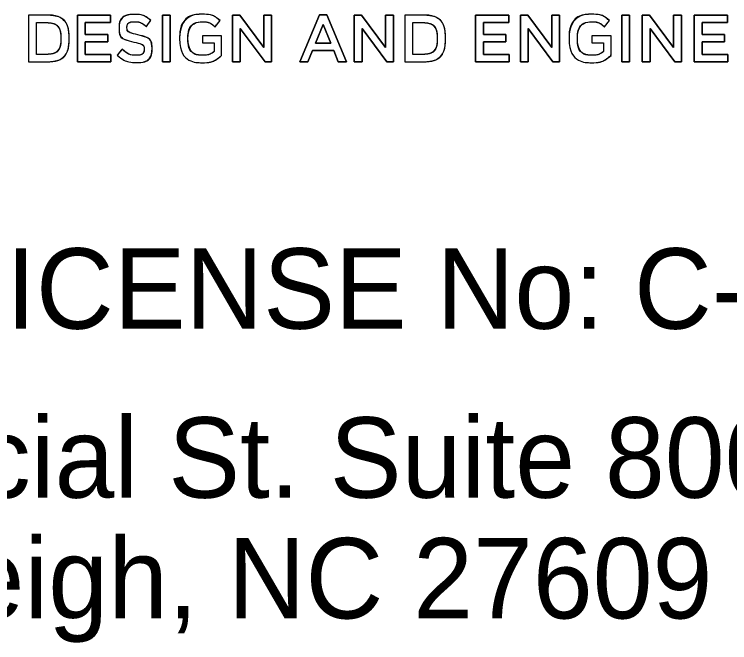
# Model space of a CAD drawing. Extents: x 1184121 to 1184360, y 1246506 to 1246661.
# Drawn here: x 1184348.947 to 1184353.836, y 1246633.134 to 1246637.429 of the extents above; entities that cross this region are included whole.
import ezdxf

# ---------------------------------------------------------------- set-up
doc = ezdxf.new("R2010")
doc.units = 0
doc.layers.add('Sheet Plan CELL', color=7, linetype='Continuous')

msp = doc.modelspace()

# ---------------------------------------------------------------- linework, layer by layer
at = {"layer": 'Sheet Plan CELL'}
for p, q in [((1184349.8503, 1246637.3459), (1184349.8793, 1246637.3884)), ((1184350.3189, 1246637.3436), (1184350.3531, 1246637.3861)), ((1184352.98, 1246637.3436), (1184353.0142, 1246637.3861)), ((1184349.6633, 1246637.3358), (1184349.6633, 1246637.3349)), ((1184349.7171, 1246637.34), (1184349.7171, 1246637.3409)), ((1184349.2652, 1246637.2641), (1184349.2652, 1246637.2632)), ((1184349.3218, 1246637.2641), (1184349.3218, 1246637.265)), ((1184350.0771, 1246637.2641), (1184350.0771, 1246637.2632)), ((1184350.1336, 1246637.2641), (1184350.1336, 1246637.265)), ((1184351.8373, 1246637.2641), (1184351.8373, 1246637.2632)), ((1184351.8938, 1246637.2641), (1184351.8938, 1246637.265)), ((1184352.7382, 1246637.2641), (1184352.7382, 1246637.2632)), ((1184352.7947, 1246637.2641), (1184352.7947, 1246637.265)), ((1184349.6834, 1246637.1911), (1184349.651, 1246637.1509)), ((1184349.8346, 1246637.1906), (1184349.8346, 1246637.1897)), ((1184349.8884, 1246637.1952), (1184349.8884, 1246637.1961))]:
    msp.add_line(p, q, dxfattribs=at)
for points in [[(1184349.1588, 1246637.424), (1184349.0444, 1246637.424), (1184349.0444, 1246637.1043), (1184349.1588, 1246637.1043)], [(1184349.3782, 1246637.424), (1184349.6055, 1246637.424), (1184349.6055, 1246637.3737), (1184349.432, 1246637.3737), (1184349.432, 1246637.2906), (1184349.5858, 1246637.2906), (1184349.5858, 1246637.2404), (1184349.432, 1246637.2404), (1184349.432, 1246637.1545), (1184349.6077, 1246637.1545), (1184349.6077, 1246637.1043), (1184349.3782, 1246637.1043), (1184349.3782, 1246637.424)], [(1184349.3782, 1246637.1043), (1184349.6077, 1246637.1043), (1184349.6077, 1246637.1545), (1184349.432, 1246637.1545), (1184349.432, 1246637.2404), (1184349.5858, 1246637.2404), (1184349.5858, 1246637.2906), (1184349.432, 1246637.2906), (1184349.432, 1246637.3737), (1184349.6055, 1246637.3737), (1184349.6055, 1246637.424), (1184349.3782, 1246637.424), (1184349.3782, 1246637.1043)], [(1184349.9593, 1246637.424), (1184350.0132, 1246637.424), (1184350.0132, 1246637.1043), (1184349.9593, 1246637.1043), (1184349.9593, 1246637.424)], [(1184349.9593, 1246637.1043), (1184350.0132, 1246637.1043), (1184350.0132, 1246637.424), (1184349.9593, 1246637.424), (1184349.9593, 1246637.1043)], [(1184350.4384, 1246637.424), (1184350.4884, 1246637.424), (1184350.6527, 1246637.2029), (1184350.6527, 1246637.424), (1184350.7057, 1246637.424), (1184350.7057, 1246637.1043), (1184350.6605, 1246637.1043), (1184350.4914, 1246637.3317), (1184350.4914, 1246637.1043), (1184350.4384, 1246637.1043), (1184350.4384, 1246637.424)], [(1184350.4384, 1246637.1043), (1184350.4914, 1246637.1043), (1184350.4914, 1246637.3317), (1184350.6605, 1246637.1043), (1184350.7057, 1246637.1043), (1184350.7057, 1246637.424), (1184350.6527, 1246637.424), (1184350.6527, 1246637.2029), (1184350.4884, 1246637.424), (1184350.4384, 1246637.424), (1184350.4384, 1246637.1043)], [(1184351.0332, 1246637.4263), (1184351.0832, 1246637.4263), (1184351.2181, 1246637.1043), (1184351.1611, 1246637.1043), (1184351.13, 1246637.1815), (1184350.985, 1246637.1815), (1184350.9535, 1246637.1043), (1184350.8983, 1246637.1043), (1184351.0332, 1246637.4263)], [(1184350.8983, 1246637.1043), (1184350.9535, 1246637.1043), (1184350.985, 1246637.1815), (1184351.13, 1246637.1815), (1184351.1611, 1246637.1043), (1184351.2181, 1246637.1043), (1184351.0832, 1246637.4263), (1184351.0332, 1246637.4263), (1184350.8983, 1246637.1043)], [(1184351.2706, 1246637.424), (1184351.3205, 1246637.424), (1184351.4847, 1246637.2029), (1184351.4847, 1246637.424), (1184351.5378, 1246637.424), (1184351.5378, 1246637.1043), (1184351.4927, 1246637.1043), (1184351.3236, 1246637.3317), (1184351.3236, 1246637.1043), (1184351.2706, 1246637.1043), (1184351.2706, 1246637.424)], [(1184351.2706, 1246637.1043), (1184351.3236, 1246637.1043), (1184351.3236, 1246637.3317), (1184351.4927, 1246637.1043), (1184351.5378, 1246637.1043), (1184351.5378, 1246637.424), (1184351.4847, 1246637.424), (1184351.4847, 1246637.2029), (1184351.3205, 1246637.424), (1184351.2706, 1246637.424), (1184351.2706, 1246637.1043)], [(1184351.7309, 1246637.424), (1184351.6166, 1246637.424), (1184351.6166, 1246637.1043), (1184351.7309, 1246637.1043)], [(1184352.0992, 1246637.424), (1184352.3265, 1246637.424), (1184352.3265, 1246637.3737), (1184352.1531, 1246637.3737), (1184352.1531, 1246637.2906), (1184352.3068, 1246637.2906), (1184352.3068, 1246637.2404), (1184352.1531, 1246637.2404), (1184352.1531, 1246637.1545), (1184352.3287, 1246637.1545), (1184352.3287, 1246637.1043), (1184352.0992, 1246637.1043), (1184352.0992, 1246637.424)], [(1184352.0992, 1246637.1043), (1184352.3287, 1246637.1043), (1184352.3287, 1246637.1545), (1184352.1531, 1246637.1545), (1184352.1531, 1246637.2404), (1184352.3068, 1246637.2404), (1184352.3068, 1246637.2906), (1184352.1531, 1246637.2906), (1184352.1531, 1246637.3737), (1184352.3265, 1246637.3737), (1184352.3265, 1246637.424), (1184352.0992, 1246637.424), (1184352.0992, 1246637.1043)], [(1184352.4058, 1246637.424), (1184352.4557, 1246637.424), (1184352.62, 1246637.2029), (1184352.62, 1246637.424), (1184352.673, 1246637.424), (1184352.673, 1246637.1043), (1184352.6279, 1246637.1043), (1184352.4588, 1246637.3317), (1184352.4588, 1246637.1043), (1184352.4058, 1246637.1043), (1184352.4058, 1246637.424)], [(1184352.4058, 1246637.1043), (1184352.4588, 1246637.1043), (1184352.4588, 1246637.3317), (1184352.6279, 1246637.1043), (1184352.673, 1246637.1043), (1184352.673, 1246637.424), (1184352.62, 1246637.424), (1184352.62, 1246637.2029), (1184352.4557, 1246637.424), (1184352.4058, 1246637.424), (1184352.4058, 1246637.1043)], [(1184353.0982, 1246637.424), (1184353.1521, 1246637.424), (1184353.1521, 1246637.1043), (1184353.0982, 1246637.1043), (1184353.0982, 1246637.424)], [(1184353.0982, 1246637.1043), (1184353.1521, 1246637.1043), (1184353.1521, 1246637.424), (1184353.0982, 1246637.424), (1184353.0982, 1246637.1043)], [(1184353.2383, 1246637.424), (1184353.2883, 1246637.424), (1184353.4525, 1246637.2029), (1184353.4525, 1246637.424), (1184353.5055, 1246637.424), (1184353.5055, 1246637.1043), (1184353.4604, 1246637.1043), (1184353.2914, 1246637.3317), (1184353.2914, 1246637.1043), (1184353.2383, 1246637.1043), (1184353.2383, 1246637.424)], [(1184353.2383, 1246637.1043), (1184353.2914, 1246637.1043), (1184353.2914, 1246637.3317), (1184353.4604, 1246637.1043), (1184353.5055, 1246637.1043), (1184353.5055, 1246637.424), (1184353.4525, 1246637.424), (1184353.4525, 1246637.2029), (1184353.2883, 1246637.424), (1184353.2383, 1246637.424), (1184353.2383, 1246637.1043)], [(1184353.5931, 1246637.424), (1184353.8204, 1246637.424), (1184353.8204, 1246637.3737), (1184353.6469, 1246637.3737), (1184353.6469, 1246637.2906), (1184353.8007, 1246637.2906), (1184353.8007, 1246637.2404), (1184353.6469, 1246637.2404), (1184353.6469, 1246637.1545), (1184353.8226, 1246637.1545), (1184353.8226, 1246637.1043), (1184353.5931, 1246637.1043), (1184353.5931, 1246637.424)], [(1184353.5931, 1246637.1043), (1184353.8226, 1246637.1043), (1184353.8226, 1246637.1545), (1184353.6469, 1246637.1545), (1184353.6469, 1246637.2404), (1184353.8007, 1246637.2404), (1184353.8007, 1246637.2906), (1184353.6469, 1246637.2906), (1184353.6469, 1246637.3737), (1184353.8204, 1246637.3737), (1184353.8204, 1246637.424), (1184353.5931, 1246637.424), (1184353.5931, 1246637.1043)], [(1184349.1588, 1246637.1554), (1184349.0983, 1246637.1554), (1184349.0983, 1246637.3728), (1184349.1588, 1246637.3728)], [(1184351.1103, 1246637.2313), (1184351.0573, 1246637.3591), (1184351.0048, 1246637.2313), (1184351.1103, 1246637.2313)], [(1184351.0048, 1246637.2313), (1184351.0573, 1246637.3591), (1184351.1103, 1246637.2313), (1184351.0048, 1246637.2313)], [(1184351.7309, 1246637.1554), (1184351.6705, 1246637.1554), (1184351.6705, 1246637.3728), (1184351.7309, 1246637.3728)], [(1184350.364, 1246637.1486), (1184350.364, 1246637.2829), (1184350.2335, 1246637.2829), (1184350.2335, 1246637.234), (1184350.312, 1246637.234), (1184350.312, 1246637.1742)], [(1184353.0251, 1246637.1486), (1184353.0251, 1246637.2829), (1184352.8945, 1246637.2829), (1184352.8945, 1246637.234), (1184352.973, 1246637.234), (1184352.973, 1246637.1742)]]:
    msp.add_lwpolyline(points, dxfattribs=at)
for points, degree in [([(1184349.0444, 1246637.424), (1184349.0444, 1246637.424), (1184349.1588, 1246637.424), (1184349.1588, 1246637.424), (1184349.2552, 1246637.424), (1184349.3218, 1246637.355), (1184349.3218, 1246637.265), (1184349.3218, 1246637.265), (1184349.3218, 1246637.2641), (1184349.3218, 1246637.2641), (1184349.3218, 1246637.1742), (1184349.2552, 1246637.1043), (1184349.1588, 1246637.1043), (1184349.1588, 1246637.1043), (1184349.0444, 1246637.1043), (1184349.0444, 1246637.1043), (1184349.0444, 1246637.1043), (1184349.0444, 1246637.424), (1184349.0444, 1246637.424)], 3), ([(1184349.3218, 1246637.265), (1184349.3218, 1246637.355), (1184349.2552, 1246637.424), (1184349.1588, 1246637.424)], 2), ([(1184349.651, 1246637.1509), (1184349.651, 1246637.1509), (1184349.6834, 1246637.1911), (1184349.6834, 1246637.1911), (1184349.7128, 1246637.1646), (1184349.7425, 1246637.1495), (1184349.7803, 1246637.1495), (1184349.8135, 1246637.1495), (1184349.8346, 1246637.166), (1184349.8346, 1246637.1897), (1184349.8346, 1246637.1897), (1184349.8346, 1246637.1906), (1184349.8346, 1246637.1906), (1184349.8346, 1246637.2134), (1184349.8223, 1246637.2258), (1184349.7653, 1246637.2395), (1184349.7001, 1246637.2559), (1184349.6633, 1246637.276), (1184349.6633, 1246637.3349), (1184349.6633, 1246637.3349), (1184349.6633, 1246637.3358), (1184349.6633, 1246637.3358), (1184349.6633, 1246637.3907), (1184349.7071, 1246637.4286), (1184349.768, 1246637.4286), (1184349.8127, 1246637.4286), (1184349.8481, 1246637.4144), (1184349.8793, 1246637.3884), (1184349.8793, 1246637.3884), (1184349.8503, 1246637.3459), (1184349.8503, 1246637.3459), (1184349.8227, 1246637.3674), (1184349.7952, 1246637.3788), (1184349.7671, 1246637.3788), (1184349.7356, 1246637.3788), (1184349.7171, 1246637.3619), (1184349.7171, 1246637.3409), (1184349.7171, 1246637.3409), (1184349.7171, 1246637.34), (1184349.7171, 1246637.34), (1184349.7171, 1246637.3153), (1184349.7312, 1246637.3043), (1184349.7903, 1246637.2897), (1184349.8551, 1246637.2733), (1184349.8884, 1246637.2491), (1184349.8884, 1246637.1961), (1184349.8884, 1246637.1961), (1184349.8884, 1246637.1952), (1184349.8884, 1246637.1952), (1184349.8884, 1246637.1354), (1184349.8433, 1246637.0997), (1184349.7789, 1246637.0997), (1184349.732, 1246637.0997), (1184349.6878, 1246637.1166), (1184349.651, 1246637.1509)], 3), ([(1184349.8793, 1246637.3884), (1184349.8481, 1246637.4144), (1184349.8127, 1246637.4286), (1184349.768, 1246637.4286), (1184349.7071, 1246637.4286), (1184349.6633, 1246637.3907), (1184349.6633, 1246637.3358)], 3), ([(1184350.0771, 1246637.2632), (1184350.0771, 1246637.2632), (1184350.0771, 1246637.2641), (1184350.0771, 1246637.2641), (1184350.0771, 1246637.3537), (1184350.1428, 1246637.4295), (1184350.2352, 1246637.4295), (1184350.2887, 1246637.4295), (1184350.3216, 1246637.4139), (1184350.3531, 1246637.3861), (1184350.3531, 1246637.3861), (1184350.3189, 1246637.3436), (1184350.3189, 1246637.3436), (1184350.2953, 1246637.3646), (1184350.2721, 1246637.3779), (1184350.2331, 1246637.3779), (1184350.1766, 1246637.3779), (1184350.1336, 1246637.3263), (1184350.1336, 1246637.265), (1184350.1336, 1246637.265), (1184350.1336, 1246637.2641), (1184350.1336, 1246637.2641), (1184350.1336, 1246637.1984), (1184350.1753, 1246637.15), (1184350.2379, 1246637.15), (1184350.2668, 1246637.15), (1184350.2931, 1246637.1596), (1184350.312, 1246637.1742), (1184350.312, 1246637.1742), (1184350.312, 1246637.234), (1184350.312, 1246637.234), (1184350.312, 1246637.234), (1184350.2335, 1246637.234), (1184350.2335, 1246637.234), (1184350.2335, 1246637.234), (1184350.2335, 1246637.2829), (1184350.2335, 1246637.2829), (1184350.2335, 1246637.2829), (1184350.364, 1246637.2829), (1184350.364, 1246637.2829), (1184350.364, 1246637.2829), (1184350.364, 1246637.1486), (1184350.364, 1246637.1486), (1184350.3338, 1246637.1216), (1184350.2905, 1246637.0988), (1184350.2362, 1246637.0988), (1184350.1402, 1246637.0988), (1184350.0771, 1246637.1701), (1184350.0771, 1246637.2632)], 3), ([(1184350.3531, 1246637.3861), (1184350.3216, 1246637.4139), (1184350.2887, 1246637.4295), (1184350.2352, 1246637.4295), (1184350.1428, 1246637.4295), (1184350.0771, 1246637.3537), (1184350.0771, 1246637.2641)], 3), ([(1184351.6166, 1246637.424), (1184351.6166, 1246637.424), (1184351.7309, 1246637.424), (1184351.7309, 1246637.424), (1184351.8272, 1246637.424), (1184351.8938, 1246637.355), (1184351.8938, 1246637.265), (1184351.8938, 1246637.265), (1184351.8938, 1246637.2641), (1184351.8938, 1246637.2641), (1184351.8938, 1246637.1742), (1184351.8272, 1246637.1043), (1184351.7309, 1246637.1043), (1184351.7309, 1246637.1043), (1184351.6166, 1246637.1043), (1184351.6166, 1246637.1043), (1184351.6166, 1246637.1043), (1184351.6166, 1246637.424), (1184351.6166, 1246637.424)], 3), ([(1184351.8938, 1246637.265), (1184351.8938, 1246637.355), (1184351.8272, 1246637.424), (1184351.7309, 1246637.424)], 2), ([(1184352.7382, 1246637.2632), (1184352.7382, 1246637.2632), (1184352.7382, 1246637.2641), (1184352.7382, 1246637.2641), (1184352.7382, 1246637.3536), (1184352.8039, 1246637.4295), (1184352.8963, 1246637.4295), (1184352.9498, 1246637.4295), (1184352.9826, 1246637.4139), (1184353.0142, 1246637.3861), (1184353.0142, 1246637.3861), (1184352.98, 1246637.3436), (1184352.98, 1246637.3436), (1184352.9563, 1246637.3646), (1184352.9331, 1246637.3779), (1184352.8941, 1246637.3779), (1184352.8376, 1246637.3779), (1184352.7947, 1246637.3263), (1184352.7947, 1246637.265), (1184352.7947, 1246637.265), (1184352.7947, 1246637.2641), (1184352.7947, 1246637.2641), (1184352.7947, 1246637.1984), (1184352.8363, 1246637.15), (1184352.8989, 1246637.15), (1184352.9279, 1246637.15), (1184352.9541, 1246637.1596), (1184352.973, 1246637.1742), (1184352.973, 1246637.1742), (1184352.973, 1246637.234), (1184352.973, 1246637.234), (1184352.973, 1246637.234), (1184352.8945, 1246637.234), (1184352.8945, 1246637.234), (1184352.8945, 1246637.234), (1184352.8945, 1246637.2829), (1184352.8945, 1246637.2829), (1184352.8945, 1246637.2829), (1184353.0251, 1246637.2829), (1184353.0251, 1246637.2829), (1184353.0251, 1246637.2829), (1184353.0251, 1246637.1486), (1184353.0251, 1246637.1486), (1184352.9949, 1246637.1216), (1184352.9515, 1246637.0988), (1184352.8972, 1246637.0988), (1184352.8013, 1246637.0988), (1184352.7382, 1246637.1701), (1184352.7382, 1246637.2632)], 3), ([(1184353.0142, 1246637.3861), (1184352.9826, 1246637.4139), (1184352.9498, 1246637.4295), (1184352.8963, 1246637.4295), (1184352.8039, 1246637.4295), (1184352.7382, 1246637.3536), (1184352.7382, 1246637.2641)], 3), ([(1184349.0983, 1246637.3728), (1184349.0983, 1246637.3728), (1184349.0983, 1246637.1554), (1184349.0983, 1246637.1554), (1184349.0983, 1246637.1554), (1184349.1588, 1246637.1554), (1184349.1588, 1246637.1554), (1184349.2232, 1246637.1554), (1184349.2652, 1246637.2007), (1184349.2652, 1246637.2632), (1184349.2652, 1246637.2632), (1184349.2652, 1246637.2641), (1184349.2652, 1246637.2641), (1184349.2652, 1246637.3267), (1184349.2232, 1246637.3728), (1184349.1588, 1246637.3728), (1184349.1588, 1246637.3728), (1184349.0983, 1246637.3728), (1184349.0983, 1246637.3728)], 3), ([(1184349.1588, 1246637.3728), (1184349.2232, 1246637.3728), (1184349.2652, 1246637.3267), (1184349.2652, 1246637.2641)], 2), ([(1184349.7171, 1246637.3409), (1184349.7171, 1246637.3619), (1184349.7356, 1246637.3788), (1184349.7671, 1246637.3788), (1184349.7952, 1246637.3788), (1184349.8227, 1246637.3674), (1184349.8503, 1246637.3459)], 3), ([(1184350.1336, 1246637.265), (1184350.1336, 1246637.3263), (1184350.1766, 1246637.3779), (1184350.2331, 1246637.3779), (1184350.2721, 1246637.3779), (1184350.2953, 1246637.3646), (1184350.3189, 1246637.3436)], 3), ([(1184351.6705, 1246637.3728), (1184351.6705, 1246637.3728), (1184351.6705, 1246637.1554), (1184351.6705, 1246637.1554), (1184351.6705, 1246637.1554), (1184351.7309, 1246637.1554), (1184351.7309, 1246637.1554), (1184351.7953, 1246637.1554), (1184351.8373, 1246637.2007), (1184351.8373, 1246637.2632), (1184351.8373, 1246637.2632), (1184351.8373, 1246637.2641), (1184351.8373, 1246637.2641), (1184351.8373, 1246637.3267), (1184351.7953, 1246637.3728), (1184351.7309, 1246637.3728), (1184351.7309, 1246637.3728), (1184351.6705, 1246637.3728), (1184351.6705, 1246637.3728)], 3), ([(1184351.7309, 1246637.3728), (1184351.7953, 1246637.3728), (1184351.8373, 1246637.3267), (1184351.8373, 1246637.2641)], 2), ([(1184352.7947, 1246637.265), (1184352.7947, 1246637.3263), (1184352.8376, 1246637.3779), (1184352.8941, 1246637.3779), (1184352.9331, 1246637.3779), (1184352.9563, 1246637.3646), (1184352.98, 1246637.3436)], 3), ([(1184349.6633, 1246637.3349), (1184349.6633, 1246637.276), (1184349.7001, 1246637.2559), (1184349.7653, 1246637.2395), (1184349.8223, 1246637.2258), (1184349.8346, 1246637.2134), (1184349.8346, 1246637.1906)], 3), ([(1184349.8884, 1246637.1961), (1184349.8884, 1246637.2491), (1184349.8551, 1246637.2733), (1184349.7903, 1246637.2897), (1184349.7312, 1246637.3043), (1184349.7171, 1246637.3153), (1184349.7171, 1246637.34)], 3), ([(1184349.1588, 1246637.1043), (1184349.2552, 1246637.1043), (1184349.3218, 1246637.1742), (1184349.3218, 1246637.2641)], 2), ([(1184349.2652, 1246637.2632), (1184349.2652, 1246637.2007), (1184349.2232, 1246637.1554), (1184349.1588, 1246637.1554)], 2), ([(1184350.0771, 1246637.2632), (1184350.0771, 1246637.1701), (1184350.1402, 1246637.0988), (1184350.2362, 1246637.0988), (1184350.2905, 1246637.0988), (1184350.3338, 1246637.1216), (1184350.364, 1246637.1486)], 3), ([(1184350.312, 1246637.1742), (1184350.2931, 1246637.1596), (1184350.2668, 1246637.15), (1184350.2379, 1246637.15), (1184350.1753, 1246637.15), (1184350.1336, 1246637.1984), (1184350.1336, 1246637.2641)], 3), ([(1184351.7309, 1246637.1043), (1184351.8272, 1246637.1043), (1184351.8938, 1246637.1742), (1184351.8938, 1246637.2641)], 2), ([(1184351.8373, 1246637.2632), (1184351.8373, 1246637.2007), (1184351.7953, 1246637.1554), (1184351.7309, 1246637.1554)], 2), ([(1184352.7382, 1246637.2632), (1184352.7382, 1246637.1701), (1184352.8013, 1246637.0988), (1184352.8972, 1246637.0988), (1184352.9515, 1246637.0988), (1184352.9949, 1246637.1216), (1184353.0251, 1246637.1486)], 3), ([(1184352.973, 1246637.1742), (1184352.9541, 1246637.1596), (1184352.9279, 1246637.15), (1184352.8989, 1246637.15), (1184352.8363, 1246637.15), (1184352.7947, 1246637.1984), (1184352.7947, 1246637.2641)], 3), ([(1184349.651, 1246637.1509), (1184349.6878, 1246637.1166), (1184349.732, 1246637.0997), (1184349.7789, 1246637.0997), (1184349.8433, 1246637.0997), (1184349.8884, 1246637.1354), (1184349.8884, 1246637.1952)], 3), ([(1184349.8346, 1246637.1897), (1184349.8346, 1246637.166), (1184349.8135, 1246637.1495), (1184349.7803, 1246637.1495), (1184349.7425, 1246637.1495), (1184349.7128, 1246637.1646), (1184349.6834, 1246637.1911)], 3)]:
    msp.add_open_spline(points, degree=degree, dxfattribs=at)

# ---------------------------------------------------------------- texts
for s, p in [('NC FIRM LICENSE No: C-5176', (1184345.2133, 1246635.2803)), ('1000 Social St. Suite 800.', (1184345.9512, 1246634.1252)), ('Raleigh, NC 27609', (1184347.5032, 1246633.3002))]:
    msp.add_text(s, height=0.55, rotation=360, dxfattribs=at).set_placement(p)

doc.saveas('drawing.dxf')
